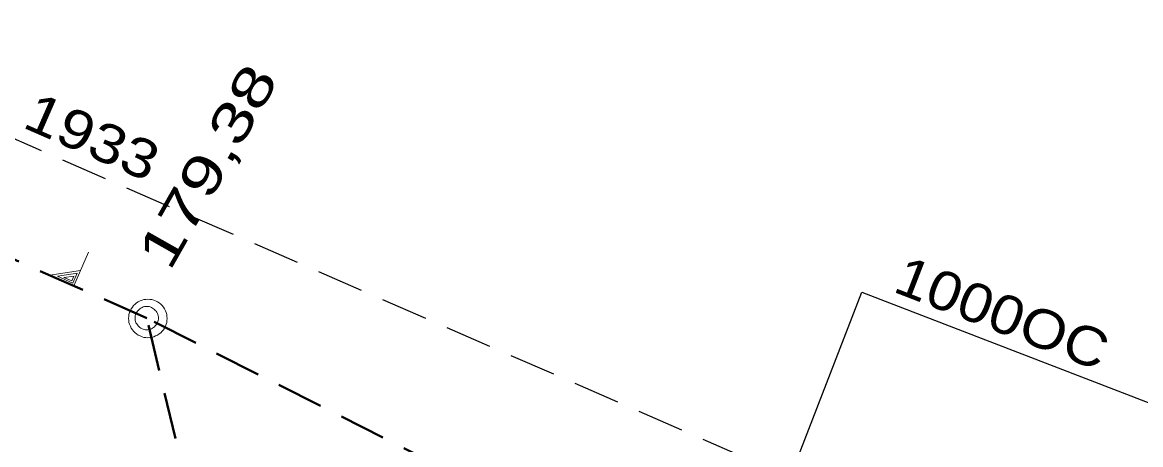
# Model space of a CAD drawing. Extents: x -740851 to -738888, y -1041382 to -1040235.
# Drawn here: x -739048.4 to -739019.6, y -1041320.97 to -1041310.09 of the extents above; entities that cross this region are included whole.
import ezdxf

# ---------------------------------------------------------------- set-up
doc = ezdxf.new("R2010")
doc.units = 0
doc.header["$LTSCALE"] = 0.4
doc.linetypes.add('MEDIUM_DASHED', pattern=[4.5, 3, -1.5])
doc.layers.add('18', color=7, linetype='Continuous', lineweight=13)
doc.layers.add('8', color=7, linetype='Continuous', lineweight=13)

msp = doc.modelspace()

# ---------------------------------------------------------------- linework, layer by layer
at = {"layer": '18', "linetype": 'MEDIUM_DASHED', "lineweight": 40}
msp.add_line((-739038.18, -1041347.07), (-739045.2, -1041317.71), dxfattribs=at)
msp.add_lwpolyline([(-739015.025, -1041332.979), (-739045.2, -1041317.71), (-739098.28, -1041294.28)], dxfattribs=at)
at = {"layer": '18'}
for points in [[(-739046.695, -1041316.013), (-739047.078, -1041316.879), (-739047.695, -1041316.606), (-739046.905, -1041316.488)], [(-739046.989, -1041316.555), (-739047.1, -1041316.807), (-739047.495, -1041316.633), (-739046.985, -1041316.557)], [(-739047.075, -1041316.626), (-739047.13, -1041316.752), (-739047.333, -1041316.662), (-739047.07, -1041316.628)]]:
    msp.add_lwpolyline(points, dxfattribs=at)
for points in [[(-739044.67, -1041317.72), (-739044.68, -1041317.67), (-739044.68, -1041317.62), (-739044.7, -1041317.57), (-739044.72, -1041317.52), (-739044.74, -1041317.47), (-739044.77, -1041317.43), (-739044.8, -1041317.39), (-739044.84, -1041317.35), (-739044.88, -1041317.32), (-739044.92, -1041317.29), (-739044.97, -1041317.27), (-739045.02, -1041317.25), (-739045.07, -1041317.23), (-739045.12, -1041317.23), (-739045.17, -1041317.22), (-739045.22, -1041317.23), (-739045.27, -1041317.23), (-739045.32, -1041317.25), (-739045.37, -1041317.27), (-739045.42, -1041317.29), (-739045.46, -1041317.32), (-739045.5, -1041317.35), (-739045.54, -1041317.39), (-739045.57, -1041317.43), (-739045.6, -1041317.47), (-739045.62, -1041317.52), (-739045.64, -1041317.57), (-739045.66, -1041317.62), (-739045.66, -1041317.67), (-739045.67, -1041317.72), (-739045.66, -1041317.77), (-739045.66, -1041317.82), (-739045.64, -1041317.87), (-739045.62, -1041317.92), (-739045.6, -1041317.97), (-739045.57, -1041318.01), (-739045.54, -1041318.05), (-739045.5, -1041318.09), (-739045.46, -1041318.12), (-739045.42, -1041318.15), (-739045.37, -1041318.17), (-739045.32, -1041318.19), (-739045.27, -1041318.21), (-739045.22, -1041318.21), (-739045.17, -1041318.22), (-739045.12, -1041318.21), (-739045.07, -1041318.21), (-739045.02, -1041318.19), (-739044.97, -1041318.17), (-739044.92, -1041318.15), (-739044.88, -1041318.12), (-739044.84, -1041318.09), (-739044.8, -1041318.05), (-739044.77, -1041318.01), (-739044.74, -1041317.97), (-739044.72, -1041317.92), (-739044.7, -1041317.87), (-739044.68, -1041317.82), (-739044.68, -1041317.77)], [(-739044.9, -1041317.71), (-739044.9, -1041317.68), (-739044.906, -1041317.65), (-739044.912, -1041317.62), (-739044.924, -1041317.59), (-739044.942, -1041317.56), (-739044.96, -1041317.536), (-739044.978, -1041317.512), (-739045.002, -1041317.488), (-739045.026, -1041317.47), (-739045.05, -1041317.452), (-739045.08, -1041317.434), (-739045.11, -1041317.422), (-739045.14, -1041317.416), (-739045.17, -1041317.41), (-739045.2, -1041317.41), (-739045.23, -1041317.41), (-739045.26, -1041317.416), (-739045.29, -1041317.422), (-739045.32, -1041317.434), (-739045.35, -1041317.452), (-739045.374, -1041317.47), (-739045.398, -1041317.488), (-739045.422, -1041317.512), (-739045.44, -1041317.536), (-739045.458, -1041317.56), (-739045.476, -1041317.59), (-739045.488, -1041317.62), (-739045.494, -1041317.65), (-739045.5, -1041317.68), (-739045.5, -1041317.71), (-739045.5, -1041317.74), (-739045.494, -1041317.77), (-739045.488, -1041317.8), (-739045.476, -1041317.83), (-739045.458, -1041317.86), (-739045.44, -1041317.884), (-739045.422, -1041317.908), (-739045.398, -1041317.932), (-739045.374, -1041317.95), (-739045.35, -1041317.968), (-739045.32, -1041317.986), (-739045.29, -1041317.998), (-739045.26, -1041318.004), (-739045.23, -1041318.01), (-739045.2, -1041318.01), (-739045.17, -1041318.01), (-739045.14, -1041318.004), (-739045.11, -1041317.998), (-739045.08, -1041317.986), (-739045.05, -1041317.968), (-739045.026, -1041317.95), (-739045.002, -1041317.932), (-739044.978, -1041317.908), (-739044.96, -1041317.884), (-739044.942, -1041317.86), (-739044.924, -1041317.83), (-739044.912, -1041317.8), (-739044.906, -1041317.77), (-739044.9, -1041317.74)]]:
    msp.add_lwpolyline(points, close=True, dxfattribs=at)
at = {"layer": '8', "lineweight": 25}
msp.add_lwpolyline([(-739030.98, -1041327.9), (-739026.78, -1041317.04), (-739010.3, -1041323.4), (-739009.27, -1041324.07), (-739006.93, -1041324.54), (-738999.34, -1041319.61), (-738973.83, -1041324.2), (-738967.89, -1041326.96), (-738912.6, -1041336.12), (-738898.9, -1041324.07), (-738902.59, -1041288.03), (-738903.44, -1041282.07), (-738902.27, -1041277.31), (-738903.16, -1041268.86), (-738902.4, -1041255.6), (-738900.82, -1041237.82), (-738900.46, -1041231.31), (-738900.36, -1041226.7), (-738895.11, -1041221.55), (-738893.11, -1041208.58), (-738893.07, -1041208.11), (-738892.71, -1041202.04)], dxfattribs=at)
at = {"layer": '8', "linetype": 'MEDIUM_DASHED', "lineweight": 25}
msp.add_lwpolyline([(-739029.766, -1041321.32), (-739082.235, -1041298.419), (-739128.51, -1041277.178), (-739131.478, -1041275.908), (-739142.38, -1041271.06)], dxfattribs=at)

# ---------------------------------------------------------------- texts
at = {"layer": '18', "width": 1.4}
msp.add_text('179,38', height=1, rotation=60.441, dxfattribs=at).set_placement((-739044.609, -1041316.532))
at = {"layer": '8'}
for s, rotation, width, p in [('1933', 336.42, 1.2, (-739048.437, -1041312.78)), ('1000OC', 338.897, 1.15, (-739026.017, -1041317.016))]:
    msp.add_text(s, height=1, rotation=rotation, dxfattribs=dict(at, width=width)).set_placement(p)

doc.saveas('drawing.dxf')
